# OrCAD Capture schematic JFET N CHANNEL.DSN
size A
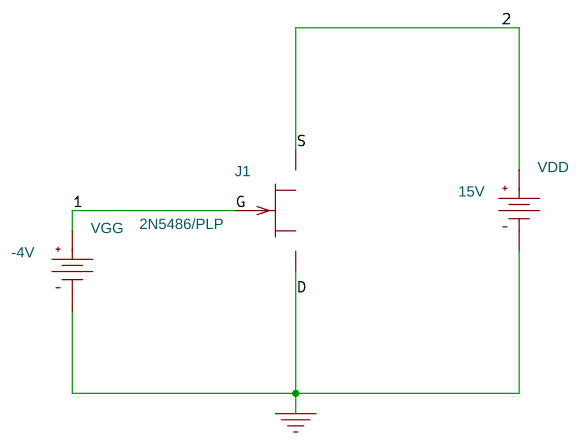
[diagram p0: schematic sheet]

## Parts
J1  2N5486/PLP  [TO92]
VDD  VDC
VGG  VDC

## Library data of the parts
J1 = 2N5486_PLP
VDD = VDC: DC: 15V
VGG = VDC: DC: -4V

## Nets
0: J1.2(s) VDD.1(-) VGG.1(-)
1: J1.3(g) VGG.0(+)
2: J1.1(d) VDD.0(+)
